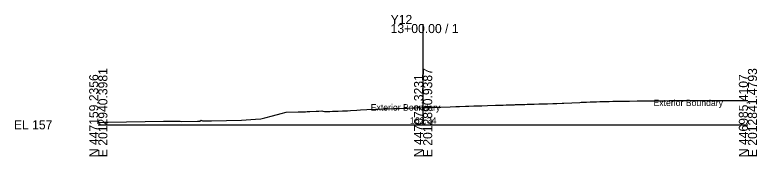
# Model space of a CAD drawing. Extents: x -26 to 1203, y -10 to 9542.
# Drawn here: x -25.7 to 202.8, y 5990.3 to 6034 of the extents above; entities that cross this region are included whole.
import ezdxf

# ---------------------------------------------------------------- set-up
doc = ezdxf.new("R2010")
doc.units = 0
for name, color, linetype in [('Default', 7, 'Continuous'), ('Exist Cross Section Cell', 7, 'Continuous'), ('Exist XS Center Line Elevation Label', 7, 'Continuous'), ('Exist XS Ground Line', 7, 'Continuous'), ('Scratch_Level_0', 7, 'Continuous')]:
    doc.layers.add(name, color=color, linetype=linetype)

msp = doc.modelspace()

# ---------------------------------------------------------------- linework, layer by layer
at = {"layer": 'Exist Cross Section Cell'}
for p, q in [((100, 6000), (100, 6031.11)), ((0, 6000), (100, 6000)), ((100, 6000), (200, 6000))]:
    msp.add_line(p, q, dxfattribs=at)
at = {"layer": 'Exist XS Ground Line'}
msp.add_lwpolyline([(0, 6000.74), (1.61, 6000.76), (3.04, 6000.79), (20.06, 6001.07), (24.1, 6001.07), (25.22, 6001.08), (25.57, 6001.05), (30.57, 6001.07), (31.27, 6001.07), (31.67, 6001.38), (32.1, 6001.21), (34.83, 6001.27), (44.04, 6001.46), (48.38, 6001.74), (50.07, 6001.89), (51.28, 6002.17), (53.64, 6002.78), (56.25, 6003.48), (57.81, 6003.85), (61.52, 6004), (61.84, 6003.99), (62.28, 6004), (62.78, 6004.01), (63.31, 6004.03), (63.81, 6004.05), (64.3, 6004.07), (65.13, 6004.1), (67.05, 6004.16), (67.89, 6004.22), (68.79, 6004.29), (69.16, 6004.21), (69.62, 6004.09), (70.81, 6004.13), (71.3, 6004.15), (72.14, 6004.18), (73.33, 6004.21), (73.84, 6004.21), (75.2, 6004.27), (76.72, 6004.35), (77.64, 6004.41), (79.6, 6004.53), (80.72, 6004.59), (82.7, 6004.68), (85.37, 6004.78), (86.21, 6004.82), (87.72, 6004.88), (88.23, 6004.9), (88.89, 6004.93), (91.09, 6005), (91.7, 6005.03), (92.75, 6005.07), (93.96, 6005.11), (95.34, 6005.16), (96.83, 6005.22), (97.19, 6005.24), (97.82, 6005.27), (100, 6005.34), (100.84, 6005.35), (102.88, 6005.4), (104.54, 6005.45), (105.49, 6005.47), (108.37, 6005.56), (110.05, 6005.62), (111.23, 6005.67), (113, 6005.73), (113.71, 6005.75), (114.12, 6005.76), (115.58, 6005.81), (116.99, 6005.86), (118.06, 6005.89), (119.87, 6005.95), (122.25, 6006.03), (122.72, 6006.04), (123.08, 6006.06), (124.68, 6006.11), (125.6, 6006.14), (126.52, 6006.17), (128.12, 6006.21), (128.48, 6006.22), (130.17, 6006.27), (131.35, 6006.3), (132.02, 6006.32), (133.17, 6006.35), (134.21, 6006.38), (135.66, 6006.42), (137.11, 6006.46), (137.53, 6006.48), (138.28, 6006.5), (139.98, 6006.57), (141.17, 6006.62), (142.85, 6006.7), (143.29, 6006.72), (145.74, 6006.83), (148.26, 6006.93), (148.62, 6006.94), (150.28, 6007), (151.47, 6007.04), (153.43, 6007.11), (154.4, 6007.14), (155.71, 6007.18), (157.27, 6007.22), (158.45, 6007.25), (160.14, 6007.29), (162.39, 6007.31), (163.02, 6007.32), (163.49, 6007.33), (165.9, 6007.36), (168.77, 6007.39), (170.53, 6007.4), (171.65, 6007.41), (172.36, 6007.42), (173.61, 6007.43), (174.54, 6007.44), (175.75, 6007.45), (177.41, 6007.47), (177.87, 6007.47), (178.68, 6007.48), (180.29, 6007.49), (181.36, 6007.49), (183.09, 6007.5), (183.45, 6007.5), (186.38, 6007.52), (187.83, 6007.53), (188.69, 6007.54), (189.9, 6007.54), (191.48, 6007.53), (191.79, 6007.54), (192.54, 6007.53), (193.85, 6007.54), (194.16, 6007.54), (194.67, 6007.54), (196.21, 6007.54), (197.54, 6007.54), (198.03, 6007.54), (198.91, 6007.54), (200, 6007.54)], dxfattribs=at)

# ---------------------------------------------------------------- texts
at = {"layer": 'Default'}
msp.add_text('-', height=0.0001, dxfattribs=at).set_placement((0, 6000))
at = {"layer": 'Exist Cross Section Cell'}
for s, p in [('Y12', (90, 6031.11)), ('13+00.00 / 1', (90, 6028.31)), ('EL 157', (-26, 5998.6))]:
    msp.add_text(s, height=2.8, dxfattribs=at).set_placement(p)
for s, p in [('E 2012940.3981', (2.8, 5990)), ('E 2012890.9387', (102.8, 5990)), ('E 2012841.4793', (202.8, 5990)), ('N 447159.2356', (0, 5990)), ('N 447072.3231', (100, 5990)), ('N 446985.4107', (200, 5990))]:
    msp.add_text(s, height=2.8, rotation=90, dxfattribs=at).set_placement(p)
at = {"layer": 'Exist XS Center Line Elevation Label'}
msp.add_text('162.34', height=2, dxfattribs=at).set_placement((95.96, 6000.34))
at = {"layer": 'Scratch_Level_0'}
for p in [(83.87, 6004.37), (170.92, 6005.78)]:
    msp.add_text('Exterior Boundary', height=2, dxfattribs=at).set_placement(p)

doc.saveas('drawing.dxf')
